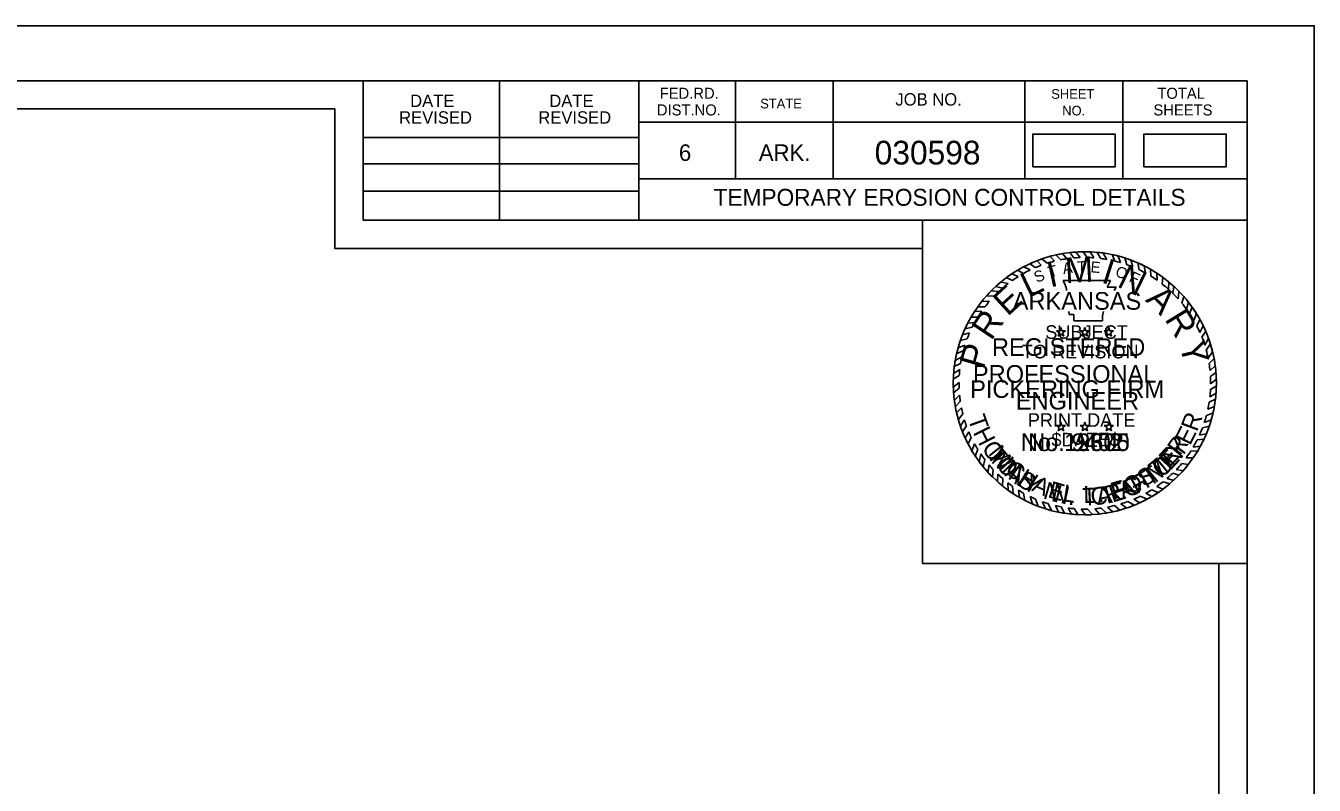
# Model space of a CAD drawing. Extents: x 814841 to 962585, y -174183 to 1802800.
# Drawn here: x 822317.1 to 822773.5, y 1802531 to 1802800.1 of the extents above; entities that cross this region are included whole.
import ezdxf

# ---------------------------------------------------------------- set-up
doc = ezdxf.new("R2010")
doc.units = 0
for name, color, linetype in [('R_Border', 7, 'Continuous'), ('R_Border Notes', 7, 'Continuous'), ('R_No Plot', 7, 'Continuous'), ('STAMP_PE_CRAFTON', 7, 'Continuous'), ('STAMP_PE_FOSTER', 7, 'Continuous'), ('STAMP_PE_SEAL-INFO', 7, 'Continuous'), ('STAMP_PE_TAEGTMEYER', 7, 'Continuous'), ('STAMP_PE_TXT', 7, 'Continuous'), ('STAMP_PRELIMINARY', 7, 'Continuous'), ('Veg Buffer', 7, 'Continuous')]:
    doc.layers.add(name, color=color, linetype=linetype)

msp = doc.modelspace()

# ---------------------------------------------------------------- linework, layer by layer
at = {"layer": 'R_Border'}
for p, q in [((821168.83, 1802780.6), (822749.73, 1802780.6)), ((822436.53, 1802731.2), (822436.53, 1802780.6)), ((822484.93, 1802731.2), (822484.93, 1802780.6)), ((822534.23, 1802780.6), (822534.23, 1802731.2)), ((822568.43, 1802780.6), (822568.43, 1802745.9)), ((822603.13, 1802780.6), (822603.13, 1802745.9)), ((822671.03, 1802780.6), (822671.03, 1802745.9)), ((822705.73, 1802780.6), (822705.73, 1802745.9)), ((822749.73, 1801753.3), (822749.73, 1802780.6)), ((822749.73, 1802765.9), (822534.23, 1802765.9)), ((822749.73, 1802766), (822749.73, 1802766)), ((822436.53, 1802760.5), (822534.23, 1802760.5)), ((822436.53, 1802751.2), (822534.23, 1802751.2)), ((822749.73, 1802745.9), (822534.23, 1802745.9)), ((822549.03, 1802745.9), (822749.73, 1802745.9)), ((822436.53, 1802741.5), (822534.23, 1802741.5)), ((822749.73, 1802731.2), (822436.53, 1802731.2))]:
    msp.add_line(p, q, dxfattribs=at)
at = {"layer": 'R_No Plot'}
for points in [[(821106.8, 1802800.08), (822773.5, 1802800.08), (822773.5, 1801733.39), (821106.8, 1801733.39)], [(822739.73, 1802276.95), (821178.83, 1802276.95), (821178.83, 1802770.6), (822426.53, 1802770.6), (822426.53, 1802721.2), (822514.23, 1802721.2), (822634.73, 1802721.2), (822634.73, 1802609.54), (822739.73, 1802609.54)], [(822739.73, 1802276.95), (821178.83, 1802276.95), (821178.83, 1802770.6), (822426.53, 1802770.6), (822426.53, 1802721.2), (822514.23, 1802721.2), (822634.73, 1802721.2), (822634.73, 1802609.54), (822739.73, 1802609.54)], [(822739.73, 1802276.95), (821178.83, 1802276.95), (821178.83, 1802770.6), (822426.53, 1802770.6), (822426.53, 1802721.2), (822514.23, 1802721.2), (822634.73, 1802721.2), (822634.73, 1802609.54), (822739.73, 1802609.54)], [(822739.73, 1802276.95), (821178.83, 1802276.95), (821178.83, 1802770.6), (822426.53, 1802770.6), (822426.53, 1802721.2), (822514.23, 1802721.2), (822634.73, 1802721.2), (822634.73, 1802609.54), (822739.73, 1802609.54)], [(822739.73, 1802276.95), (821178.83, 1802276.95), (821178.83, 1802770.6), (822426.53, 1802770.6), (822426.53, 1802721.2), (822514.23, 1802721.2), (822634.73, 1802721.2), (822634.73, 1802609.54), (822739.73, 1802609.54)], [(822739.73, 1802276.95), (821178.83, 1802276.95), (821178.83, 1802770.6), (822426.53, 1802770.6), (822426.53, 1802721.2), (822514.23, 1802721.2), (822634.73, 1802721.2), (822634.73, 1802609.54), (822739.73, 1802609.54)], [(821178.83, 1802770.6), (822426.53, 1802770.6), (822426.53, 1802721.2), (822514.23, 1802721.2), (822634.73, 1802721.2), (822634.73, 1802609.54), (822739.73, 1802609.54), (822739.73, 1801763.3), (821178.83, 1801763.3)], [(822739.73, 1802276.95), (821178.83, 1802276.95), (821178.83, 1802770.6), (822426.53, 1802770.6), (822426.53, 1802721.2), (822514.23, 1802721.2), (822634.73, 1802721.2), (822634.73, 1802609.54), (822739.73, 1802609.54)], [(822634.73, 1802731.2), (822749.73, 1802731.2), (822749.73, 1802609.54), (822634.73, 1802609.54)]]:
    msp.add_lwpolyline(points, close=True, dxfattribs=at)
at = {"layer": 'STAMP_PE_SEAL-INFO'}
for p, q in [((822684.34, 1802719.36), (822685.83, 1802717.52)), ((822686.92, 1802719.72), (822688.32, 1802717.81)), ((822690.59, 1802717.95), (822689.03, 1802719.92)), ((822693.08, 1802717.98), (822691.69, 1802720.03)), ((822695.37, 1802717.87), (822694.08, 1802719.99)), ((822697.9, 1802717.62), (822696.44, 1802719.84)), ((822700.03, 1802717.3), (822698.74, 1802719.57)), ((822702.84, 1802716.7), (822701.97, 1802719)), ((822670.6, 1802714.7), (822672.92, 1802713.58)), ((822672.75, 1802715.76), (822674.7, 1802714.39)), ((822675.29, 1802716.84), (822676.77, 1802715.21)), ((822677.03, 1802717.48), (822678.93, 1802715.95)), ((822679.99, 1802718.39), (822681.43, 1802716.65)), ((822681.93, 1802718.88), (822683.7, 1802717.16)), ((822704.85, 1802716.16), (822704.05, 1802718.51)), ((822707.11, 1802715.43), (822706.4, 1802717.82)), ((822709.2, 1802714.63), (822708.48, 1802717.11)), ((822711.51, 1802713.6), (822710.99, 1802716.09)), ((822713.73, 1802712.45), (822713.3, 1802715)), ((822664.32, 1802710.9), (822666.6, 1802709.87)), ((822666.42, 1802712.23), (822668.63, 1802711.22)), ((822668.36, 1802713.45), (822670.52, 1802712.34)), ((822684.6, 1802709.87), (822701.32, 1802709.87)), ((822685.21, 1802708.34), (822684.6, 1802709.87)), ((822701.32, 1802709.87), (822700.19, 1802707.41)), ((822715.67, 1802711.32), (822715.47, 1802713.82)), ((822717.85, 1802709.89), (822717.69, 1802712.46)), ((822719.65, 1802708.55), (822719.82, 1802710.99)), ((822659.04, 1802706.14), (822661.76, 1802705.94)), ((822660.72, 1802707.76), (822663.01, 1802707.07)), ((822662.44, 1802709.26), (822665.08, 1802708.76)), ((822685.73, 1802706.85), (822685.21, 1802708.34)), ((822685.76, 1802706.28), (822685.73, 1802706.85)), ((822700.19, 1802707.41), (822703.36, 1802707.41)), ((822703.36, 1802707.41), (822702.63, 1802706.28)), ((822721.88, 1802706.69), (822721.98, 1802709.31)), ((822723.44, 1802705.23), (822723.79, 1802707.72)), ((822725.24, 1802703.36), (822725.57, 1802705.99)), ((822655.7, 1802702.37), (822658.45, 1802702.48)), ((822657.43, 1802704.42), (822660.04, 1802704.23)), ((822726.61, 1802701.78), (822727.29, 1802704.14)), ((822728.23, 1802699.7), (822728.9, 1802702.19)), ((822651.91, 1802696.79), (822654.35, 1802696.89)), ((822653.14, 1802698.8), (822655.72, 1802698.97)), ((822654.31, 1802700.52), (822656.83, 1802700.49)), ((822686.72, 1802697.73), (822686.59, 1802698.82)), ((822688.29, 1802697.73), (822686.72, 1802697.73)), ((822688.29, 1802695.58), (822688.29, 1802697.73)), ((822698.52, 1802697.27), (822698.44, 1802695.58)), ((822698.9, 1802698.82), (822698.52, 1802697.27)), ((822729.33, 1802698.12), (822730.22, 1802700.44)), ((822730.87, 1802695.63), (822731.78, 1802698.09)), ((822649.81, 1802692.73), (822652.32, 1802693.25)), ((822650.75, 1802694.68), (822653.24, 1802695)), ((822698.44, 1802695.58), (822688.29, 1802695.58)), ((822731.87, 1802693.8), (822733, 1802696.02)), ((822733.02, 1802691.38), (822734.15, 1802693.81)), ((822733.72, 1802689.7), (822735.04, 1802691.86)), ((822648.14, 1802688.54), (822650.56, 1802689.22)), ((822648.89, 1802690.57), (822651.41, 1802691.3)), ((822734.7, 1802686.95), (822736.05, 1802689.32)), ((822735.23, 1802685.13), (822736.7, 1802687.39)), ((822648.66, 1802682.75), (822646.33, 1802681.51)), ((822646.83, 1802683.99), (822649.18, 1802684.95)), ((822647.36, 1802686.02), (822649.74, 1802686.87)), ((822735.9, 1802682.33), (822737.49, 1802684.57)), ((822647.93, 1802678.28), (822645.75, 1802676.88)), ((822648.23, 1802680.46), (822646, 1802679.35)), ((822736.25, 1802680.43), (822738.01, 1802682.2)), ((822736.58, 1802677.89), (822738.44, 1802679.57)), ((822647.75, 1802676.16), (822645.64, 1802674.87)), ((822647.67, 1802673.69), (822645.64, 1802672.01)), ((822736.74, 1802675.8), (822738.69, 1802677.26)), ((822736.8, 1802673.21), (822738.83, 1802674.82)), ((822647.7, 1802671.66), (822645.74, 1802670.03)), ((822647.87, 1802669.18), (822646.01, 1802667.4)), ((822736.55, 1802668.65), (822738.72, 1802669.93)), ((822736.75, 1802671.18), (822738.84, 1802672.57)), ((822648.13, 1802667.03), (822646.36, 1802665.17)), ((822648.52, 1802664.74), (822646.82, 1802662.9)), ((822735.84, 1802664.21), (822738.12, 1802665.19)), ((822736.29, 1802666.71), (822738.51, 1802667.81)), ((822648.99, 1802662.64), (822647.43, 1802660.57)), ((822649.61, 1802660.41), (822648.13, 1802658.32)), ((822734.57, 1802659.48), (822737.02, 1802660.48)), ((822735.3, 1802661.95), (822737.66, 1802662.96)), ((822650.31, 1802658.29), (822648.9, 1802656.23)), ((822651.14, 1802656.16), (822649.83, 1802654.05)), ((822732.82, 1802655.01), (822735.26, 1802655.49)), ((822733.89, 1802657.58), (822736.31, 1802658.23)), ((822652, 1802654.24), (822650.86, 1802651.94)), ((822653.17, 1802651.95), (822652.22, 1802649.5)), ((822730.66, 1802650.83), (822733.16, 1802651.1)), ((822732.02, 1802653.33), (822734.46, 1802653.67)), ((822654.35, 1802649.93), (822653.43, 1802647.58)), ((822655.37, 1802648.38), (822654.82, 1802645.62)), ((822656.77, 1802646.42), (822656.26, 1802643.77)), ((822728.1, 1802646.96), (822730.62, 1802646.97)), ((822729.8, 1802649.43), (822732.18, 1802649.4)), ((822658.29, 1802644.54), (822657.86, 1802641.94)), ((822659.8, 1802642.85), (822659.49, 1802640.24)), ((822723.37, 1802641.53), (822725.57, 1802640.84)), ((822724.64, 1802642.82), (822727.03, 1802642.4)), ((822726.56, 1802644.99), (822728.87, 1802644.59)), ((822661.41, 1802641.22), (822661.27, 1802638.58)), ((822663.14, 1802639.66), (822663.12, 1802637.01)), ((822664.94, 1802638.19), (822665.03, 1802635.56)), ((822666.63, 1802636.94), (822666.81, 1802634.35)), ((822717.68, 1802636.83), (822719.88, 1802635.88)), ((822719.99, 1802638.54), (822722.33, 1802637.82)), ((822721.34, 1802639.67), (822723.7, 1802639.02)), ((822668.76, 1802635.53), (822669.07, 1802632.97)), ((822670.52, 1802634.5), (822670.97, 1802631.93)), ((822672.92, 1802633.25), (822673.7, 1802630.64)), ((822674.78, 1802632.41), (822675.65, 1802629.85)), ((822709.56, 1802632.35), (822711.67, 1802631.05)), ((822711.85, 1802633.4), (822714.27, 1802632.34)), ((822713.89, 1802634.47), (822715.98, 1802633.3)), ((822715.96, 1802635.69), (822718.21, 1802634.71)), ((822677.25, 1802631.44), (822678.29, 1802628.94)), ((822679.29, 1802630.77), (822680.43, 1802628.32)), ((822681.83, 1802630.08), (822682.9, 1802627.75)), ((822683.82, 1802629.65), (822685.05, 1802627.36)), ((822686.32, 1802629.24), (822687.52, 1802627.04)), ((822688.51, 1802629), (822689.88, 1802626.86)), ((822690.93, 1802628.87), (822692.44, 1802626.8)), ((822693.23, 1802628.86), (822694.95, 1802626.88)), ((822695.82, 1802628.99), (822697.45, 1802627.09)), ((822698.01, 1802629.22), (822699.88, 1802627.43)), ((822700.24, 1802629.57), (822702.18, 1802627.88)), ((822702.7, 1802630.09), (822704.59, 1802628.47)), ((822705, 1802630.72), (822707.08, 1802629.23)), ((822707.46, 1802631.53), (822709.68, 1802630.19))]:
    msp.add_line(p, q, dxfattribs=at)
for radius, start, end in [(46.61, 99.7525, 102.7765), (46.61, 93.9381, 96.5517), (46.61, 87.7298, 90.6707), (46.61, 81.9732, 84.8236), (46.61, 75.3125, 77.9426), (46.61, 117.6544, 120.8099), (46.61, 111.3124, 114.7026), (44.57, 110.3086, 113.1659), (46.61, 105.2339, 109.0352), (44.57, 104.0352, 107.3615), (44.57, 98.258, 101.0329), (44.57, 92.1102, 95.0367), (44.57, 85.9628, 88.9097), (44.57, 79.9264, 82.696), (44.57, 73.5575, 76.2314), (46.61, 69.6061, 72.3058), (44.57, 67.6248, 70.504), (46.61, 63.1329, 66.2704), (46.61, 123.6199, 126.5906), (44.57, 121.9746, 125.11), (44.57, 115.6869, 119.1583), (44.57, 61.1558, 64.3784), (46.61, 56.9003, 60.0942), (44.57, 54.9238, 58.2702), (46.61, 50.3492, 53.7159), (46.61, 135.4021, 138.3031), (44.57, 133.1331, 136.2562), (46.61, 129.7326, 132.5376), (44.57, 127.5297, 130.9683), (44.57, 48.3016, 52.0395), (46.61, 44.3405, 47.3929), (46.61, 141.6056, 144.4486), (44.57, 139.301, 142.5873), (44.57, 42.2212, 45.5512), (44.57, 36.135, 39.5311), (46.61, 38.1247, 41.2316), (46.61, 147.0072, 149.899), (44.57, 145.0197, 148.2104), (44.57, 29.9032, 33.6645), (46.61, 31.9614, 35.4294), (46.61, 152.864, 155.5189), (44.57, 151.0315, 153.573), (44.57, 23.7732, 27.2211), (46.61, 25.9391, 29.0125), (46.61, 19.9538, 23.3141), (46.61, 158.4077, 161.0701), (44.57, 156.3402, 159.2319), (44.57, 17.6802, 21.4251), (46.61, 13.8421, 17.4447), (46.61, 164.3068, 166.894), (44.57, 167.9048, 170.9039), (44.57, 162.4331, 165.0013), (44.57, 11.5444, 15.2364), (46.61, 170.0003, 172.6878), (44.57, 173.73, 176.4734), (44.57, 5.7599, 9.0606), (46.61, 7.5852, 10.8621), (46.61, 175.7409, 178.2066), (44.57, 179.6454, 182.2633), (44.57, 359.7329, 3.0639), (46.61, 1.7215, 4.7268), (46.61, 181.7251, 184.1626), (44.57, 185.4539, 188.234), (44.57, 353.8632, 357.1274), (46.61, 355.7156, 358.9569), (46.61, 187.4204, 190.1927), (44.57, 191.2274, 193.9858), (44.57, 348.0778, 351.3435), (46.61, 349.8305, 353.0885), (46.61, 193.0369, 195.9973), (44.57, 196.9675, 199.8353), (44.57, 341.777, 345.0925), (46.61, 343.8925, 347.035), (46.61, 198.8967, 201.6281), (44.57, 202.7761, 205.4791), (44.57, 335.6038, 339.1858), (46.61, 337.3837, 340.9933), (46.61, 204.5479, 207.4328), (44.57, 208.7883, 211.7934), (44.57, 329.5549, 333.2076), (46.61, 331.4037, 334.9332), (46.61, 210.8636, 213.6571), (44.57, 214.1838, 217.2747), (44.57, 323.5851, 327.4407), (46.61, 325.4405, 328.9872), (46.61, 216.6115, 219.491), (46.61, 222.48, 225.3801), (44.57, 220.3909, 223.3056), (44.57, 310.7744, 314.3161), (44.57, 316.6531, 320.3711), (46.61, 318.2846, 321.8043), (46.61, 228.3665, 231.348), (44.57, 226.2494, 229.2407), (44.57, 232.229, 234.9336), (44.57, 304.823, 308.5143), (46.61, 306.3721, 310.208), (46.61, 312.4518, 315.6633), (46.61, 234.295, 236.9452), (44.57, 238.2223, 240.8353), (46.61, 240.1977, 242.8613), (44.57, 244.3204, 246.9486), (44.57, 292.8745, 296.1185), (46.61, 294.6481, 298.2166), (44.57, 299.0768, 302.1724), (46.61, 300.621, 303.8703), (46.61, 246.576, 249.1558), (44.57, 250.3491, 253.1216), (46.61, 252.5967, 255.3252), (44.57, 256.505, 259.1192), (46.61, 258.4433, 261.1398), (44.57, 262.3783, 265.2012), (44.57, 268.3215, 271.277), (44.57, 274.6157, 277.4486), (44.57, 280.3459, 283.5814), (46.61, 282.3199, 285.3702), (44.57, 286.6423, 289.9783), (46.61, 288.5709, 291.9733), (46.61, 264.1978, 267.1009), (46.61, 270.2548, 273.3361), (46.61, 276.4239, 279.4357)]:
    msp.add_arc((822692.23, 1802673.42), radius, start, end, dxfattribs=at)
at = {"layer": 'STAMP_PE_TXT'}
for p, q in [((822683.13, 1802691.27), (822682.14, 1802691.99)), ((822682.14, 1802691.99), (822683.37, 1802691.99)), ((822683.37, 1802691.99), (822683.74, 1802693.16)), ((822683.74, 1802693.16), (822684.12, 1802691.99)), ((822684.12, 1802691.99), (822685.35, 1802691.99)), ((822685.35, 1802691.99), (822684.36, 1802691.27)), ((822691.62, 1802691.27), (822690.63, 1802691.99)), ((822690.63, 1802691.99), (822691.86, 1802691.99)), ((822691.86, 1802691.99), (822692.23, 1802693.16)), ((822692.23, 1802693.16), (822692.61, 1802691.99)), ((822692.61, 1802691.99), (822693.84, 1802691.99)), ((822693.84, 1802691.99), (822692.85, 1802691.27)), ((822700.11, 1802691.27), (822699.12, 1802691.99)), ((822699.12, 1802691.99), (822700.34, 1802691.99)), ((822700.34, 1802691.99), (822700.72, 1802693.16)), ((822700.72, 1802693.16), (822701.1, 1802691.99)), ((822701.1, 1802691.99), (822702.33, 1802691.99)), ((822702.33, 1802691.99), (822701.34, 1802691.27)), ((822682.75, 1802690.11), (822683.13, 1802691.27)), ((822683.74, 1802690.83), (822682.75, 1802690.11)), ((822684.74, 1802690.11), (822683.74, 1802690.83)), ((822684.36, 1802691.27), (822684.74, 1802690.11)), ((822691.24, 1802690.11), (822691.62, 1802691.27)), ((822692.23, 1802690.83), (822691.24, 1802690.11)), ((822693.23, 1802690.11), (822692.23, 1802690.83)), ((822692.85, 1802691.27), (822693.23, 1802690.11)), ((822699.73, 1802690.11), (822700.11, 1802691.27)), ((822700.72, 1802690.83), (822699.73, 1802690.11)), ((822701.72, 1802690.11), (822700.72, 1802690.83)), ((822701.34, 1802691.27), (822701.72, 1802690.11)), ((822683.37, 1802658.46), (822683.74, 1802659.62)), ((822683.74, 1802659.62), (822684.12, 1802658.46)), ((822691.86, 1802658.46), (822692.23, 1802659.62)), ((822692.23, 1802659.62), (822692.61, 1802658.46)), ((822700.34, 1802658.46), (822700.72, 1802659.62)), ((822700.72, 1802659.62), (822701.1, 1802658.46)), ((822683.13, 1802657.74), (822682.14, 1802658.46)), ((822682.14, 1802658.46), (822683.37, 1802658.46)), ((822682.75, 1802656.57), (822683.13, 1802657.74)), ((822683.74, 1802657.29), (822682.75, 1802656.57)), ((822684.74, 1802656.57), (822683.74, 1802657.29)), ((822684.12, 1802658.46), (822685.35, 1802658.46)), ((822685.35, 1802658.46), (822684.36, 1802657.74)), ((822684.36, 1802657.74), (822684.74, 1802656.57)), ((822691.62, 1802657.74), (822690.63, 1802658.46)), ((822690.63, 1802658.46), (822691.86, 1802658.46)), ((822691.24, 1802656.57), (822691.62, 1802657.74)), ((822692.23, 1802657.29), (822691.24, 1802656.57)), ((822693.23, 1802656.57), (822692.23, 1802657.29)), ((822692.61, 1802658.46), (822693.84, 1802658.46)), ((822693.84, 1802658.46), (822692.85, 1802657.74)), ((822692.85, 1802657.74), (822693.23, 1802656.57)), ((822700.11, 1802657.74), (822699.12, 1802658.46)), ((822699.12, 1802658.46), (822700.34, 1802658.46)), ((822699.73, 1802656.57), (822700.11, 1802657.74)), ((822700.72, 1802657.29), (822699.73, 1802656.57)), ((822701.72, 1802656.57), (822700.72, 1802657.29)), ((822701.1, 1802658.46), (822702.33, 1802658.46)), ((822702.33, 1802658.46), (822701.34, 1802657.74)), ((822701.34, 1802657.74), (822701.72, 1802656.57))]:
    msp.add_line(p, q, dxfattribs=at)
at = {"layer": 'STAMP_PRELIMINARY'}
msp.add_circle((822692.23, 1802673.42), 46.61, dxfattribs=at)
at = {"layer": 'Veg Buffer'}
for points in [[(822673.8, 1802750.13), (822702.97, 1802750.13), (822702.97, 1802761.68), (822673.8, 1802761.68)], [(822713.15, 1802750.13), (822742.32, 1802750.13), (822742.32, 1802761.68), (822713.15, 1802761.68)]]:
    msp.add_lwpolyline(points, close=True, dxfattribs=at)

# ---------------------------------------------------------------- texts
at = {"layer": 'R_Border'}
for s, height, p in [('DATE', 4.396, (822453.22, 1802771.28)), ('DATE', 4.396, (822502.52, 1802771.28)), ('FED.RD.', 3.91, (822541.63, 1802774.2)), ('STATE', 3.42, (822577.23, 1802770.8)), ('JOB NO.', 4.396, (822625.13, 1802771.8)), ('SHEET', 3.42, (822680.33, 1802774.2)), ('TOTAL', 3.91, (822717.93, 1802774.2)), ('REVISED', 4.396, (822449.32, 1802765.38)), ('REVISED', 4.396, (822498.62, 1802765.38)), ('DIST.NO.', 3.91, (822540.63, 1802768.3)), ('NO.', 3.42, (822684.23, 1802768.3)), ('SHEETS', 3.91, (822716.53, 1802768.3)), ('6', 5.86, (822548.43, 1802752.2)), ('ARK.', 5.861, (822576.73, 1802752.2))]:
    msp.add_text(s, height=height, dxfattribs=at).set_placement(p)
at = {"layer": 'R_Border Notes'}
for s, height, p in [('030598', 8.4, (822617.79, 1802750.93)), ('TEMPORARY EROSION CONTROL DETAILS', 6, (822560.74, 1802736.3))]:
    msp.add_text(s, height=height, dxfattribs=at).set_placement(p)
at = {"layer": 'STAMP_PE_CRAFTON'}
msp.add_text('No. 12370', height=6.25, dxfattribs=at).set_placement((822669.54, 1802649.4))
for s, rotation, p in [('T', 310.7442, (822657.06, 1802647.9)), ('N', 49.2411, (822723.65, 1802643.53)), ('O', 317.6422, (822660.4, 1802643.85)), ('O', 41.8391, (822719.41, 1802639.62)), ('N', 324.4537, (822664.63, 1802639.92)), ('Y', 331.1686, (822669.79, 1802636.34)), ('F', 28.7821, (822710.54, 1802634.06)), ('T', 34.1136, (822715.12, 1802636.61)), ('N', 347.4752, (822680.07, 1802631.76)), ('C', 6.0117, (822694.59, 1802630.12)), ('R', 14.8189, (822700.07, 1802630.7)), ('A', 20.5125, (822705.64, 1802632.19)), ('.', 356.8926, (822686.21, 1802630.38))]:
    msp.add_text(s, height=6.25, rotation=rotation, dxfattribs=at).set_placement(p)
at = {"layer": 'STAMP_PE_FOSTER'}
msp.add_text('No. 9402', height=6.25, dxfattribs=at).set_placement((822672.16, 1802649.4))
for s, rotation, p in [('M', 308.339, (822657.81, 1802648.53)), ('E', 46.9613, (822722.24, 1802643.37)), ('R', 54.5031, (822725.86, 1802647.47)), ('I', 314.1842, (822661.8, 1802643.84)), ('T', 39.4194, (822717.95, 1802639.62)), ('C', 319.8733, (822663.57, 1802642.07)), ('H', 327.7235, (822668.22, 1802638.39)), ('S', 31.7234, (822713.19, 1802636.48)), ('A', 335.7276, (822673.12, 1802635.48)), ('E', 343.5779, (822678.81, 1802633.13)), ('L', 350.8115, (822684.1, 1802631.74)), ('L', 1.2666, (822691.8, 1802630.96)), ('F', 15.8691, (822702.41, 1802632.19)), ('O', 23.719, (822707.63, 1802633.83)), ('.', 6.8035, (822697.03, 1802631.25))]:
    msp.add_text(s, height=6, rotation=rotation, dxfattribs=at).set_placement(p)
at = {"layer": 'STAMP_PE_TAEGTMEYER'}
for s, rotation, p in [('T', 289.646, (822650.71, 1802660.97)), ('R', 69.57, (822731.96, 1802655.99)), ('H', 296.7339, (822652.51, 1802656.04)), ('E', 63.0984, (822729.47, 1802651.08)), ('O', 303.7708, (822655.47, 1802650.5)), ('Y', 53.9986, (822726.12, 1802646.38)), ('M', 314.2033, (822658.74, 1802645.75)), ('M', 39.3, (822717.22, 1802637.91)), ('E', 46.8094, (822722.43, 1802642.3)), ('A', 321.0594, (822663.55, 1802640.93)), ('S', 327.8239, (822667.68, 1802637.71)), ('T', 31.466, (822712.73, 1802635.19)), ('N', 344.2727, (822677.17, 1802632.67)), ('A', 8.9826, (822696.79, 1802630.3)), ('E', 17.6836, (822701.98, 1802631.07)), ('G', 23.3052, (822707.23, 1802632.73)), ('T', 3.0061, (822691.55, 1802630.02)), ('.', 350.6464, (822683.23, 1802631.01))]:
    msp.add_text(s, height=6.25, rotation=rotation, dxfattribs=at).set_placement(p)
msp.add_text('No. 19605', height=6.25, dxfattribs=at).set_placement((822669.54, 1802649.4))
at = {"layer": 'STAMP_PE_TXT'}
for s, rotation, p in [('T', 16.311, (822679.84, 1802710.8)), ('A', 9.0679, (822684.65, 1802712.06)), ('T', 1.8248, (822689.59, 1802712.71)), ('E', 355.2002, (822694.14, 1802712.75)), ('O', 342.2506, (822702.77, 1802711.37)), ('S', 23.5541, (822675.23, 1802708.93)), ('F', 335.0075, (822707.6, 1802709.68))]:
    msp.add_text(s, height=3.91, rotation=rotation, dxfattribs=at).set_placement(p)
for s, p in [('ARKANSAS', (822666.7, 1802699.47)), ('REGISTERED', (822659.32, 1802683.12)), ('PROFESSIONAL', (822652.58, 1802673.61)), ('ENGINEER', (822667.78, 1802664.11))]:
    msp.add_text(s, height=6.25, dxfattribs=at).set_placement(p)
at = {"layer": 'STAMP_PRELIMINARY'}
for s, rotation, p in [('I', 12.5248, (822679.92, 1802707.35)), ('M', 3.1074, (822685.41, 1802708.89)), ('I', 342.3164, (822697.75, 1802709.23)), ('N', 333.9382, (822703.29, 1802707.86)), ('L', 25.513, (822672.28, 1802703.55)), ('E', 42.3578, (822664.86, 1802696.9)), ('A', 315.6579, (822713.46, 1802702.73)), ('R', 56.2292, (822659.09, 1802688.23)), ('R', 301.3831, (822720.3, 1802696.16)), ('P', 73.913, (822656.34, 1802678.12)), ('Y', 283.2593, (822725.74, 1802687.23))]:
    msp.add_text(s, height=9, rotation=rotation, dxfattribs=at).set_placement(p)
for s, height, p in [('SUBJECT', 4.8, (822678.23, 1802689.16)), ('TO REVISION', 4.8, (822669.91, 1802682.24)), ('PICKERING FIRM', 6.25, (822651.6, 1802668.23)), ('PRINT DATE', 4.8, (822672.02, 1802657.99)), ('$DATE$', 4.8, (822680.4, 1802651.07))]:
    msp.add_text(s, height=height, dxfattribs=at).set_placement(p)

doc.saveas('drawing.dxf')
